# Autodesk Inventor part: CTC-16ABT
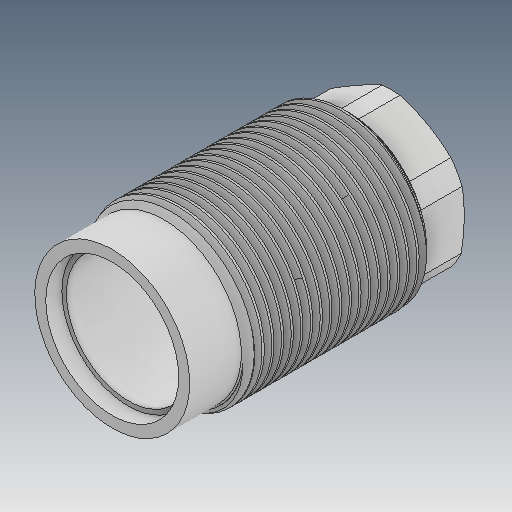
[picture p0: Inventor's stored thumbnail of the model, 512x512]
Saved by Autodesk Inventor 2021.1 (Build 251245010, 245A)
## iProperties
Created: 2018-08
Part Number: CTC-16ABT
Material: Ogólny
Document SubType Name: Modeling
Designer: user
Density: 1 g/cm^3
Appearance: Domyślna
Author: user
Revision Number: ÈÎºÎ
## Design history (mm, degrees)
feature "ÊäÈë1"
node "Bryła1"
